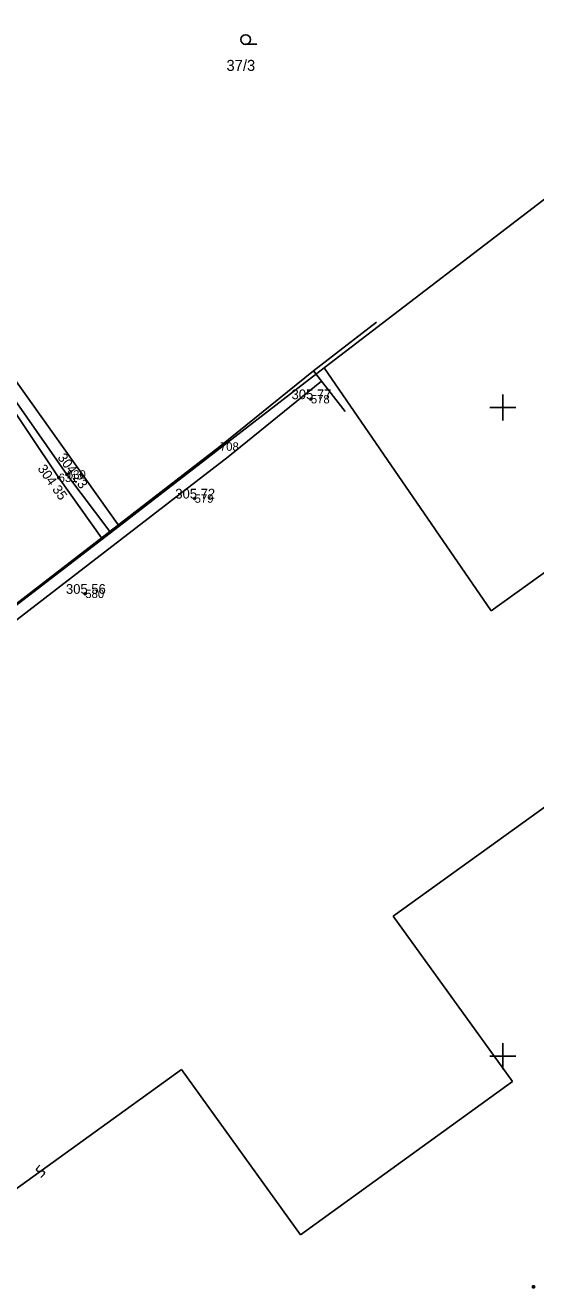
# Model space of a CAD drawing. Extents: x -492811 to -492366, y -1127107 to -1126748.
# Drawn here: x -492594.72 to -492578.99, y -1126927.14 to -1126888.22 of the extents above; entities that cross this region are included whole.
import ezdxf

# ---------------------------------------------------------------- set-up
doc = ezdxf.new("R2010")
doc.units = 0
for name, color, linetype in [('body', 7, 'Continuous'), ('katastrální mapa', 7, 'Continuous'), ('oplocení', 7, 'Continuous'), ('opěrná zeď', 7, 'Continuous'), ('podrobný výškový bod', 7, 'Continuous'), ('rozhraní ploch', 7, 'Continuous'), ('stavební objekt', 7, 'Continuous'), ('síť', 7, 'Continuous'), ('výšky', 7, 'Continuous'), ('čísla bodů', 7, 'Continuous')]:
    doc.layers.add(name, color=color, linetype=linetype)

msp = doc.modelspace()

# ---------------------------------------------------------------- linework, layer by layer
at = {"layer": 'body'}
for p, q in [((-492585.92, -1126899.748), (-492585.92, -1126899.748)), ((-492588.722, -1126901.209), (-492588.722, -1126901.209)), ((-492593.438, -1126902.068), (-492593.438, -1126902.068)), ((-492593.692, -1126902.171), (-492593.692, -1126902.171)), ((-492589.502, -1126902.811), (-492589.502, -1126902.811)), ((-492592.872, -1126905.748), (-492592.872, -1126905.748))]:
    msp.add_line(p, q, dxfattribs=at)
at = {"layer": 'katastrální mapa'}
for p, q in [((-492602.83, -1126888.22), (-492591.83, -1126903.66)), ((-492587.931, -1126888.807), (-492587.581, -1126888.807)), ((-492585.51, -1126898.78), (-492577.3, -1126892.49)), ((-492591.83, -1126903.66), (-492585.51, -1126898.78)), ((-492585.51, -1126898.78), (-492580.36, -1126906.27)), ((-492580.36, -1126906.27), (-492571.79, -1126900.09)), ((-492606.11, -1126914.64), (-492591.83, -1126903.66)), ((-492583.38, -1126915.69), (-492574.79, -1126909.49)), ((-492583.38, -1126915.69), (-492579.71, -1126920.78)), ((-492598.6, -1126926.69), (-492589.91, -1126920.41)), ((-492589.91, -1126920.41), (-492586.24, -1126925.51)), ((-492586.24, -1126925.51), (-492579.71, -1126920.78)), ((-492594.37, -1126923.46), (-492594.38, -1126923.52)), ((-492594.38, -1126923.52), (-492594.35, -1126923.55)), ((-492594.27, -1126923.36), (-492594.37, -1126923.46)), ((-492594.3, -1126923.56), (-492594.21, -1126923.54)), ((-492594.21, -1126923.54), (-492594.16, -1126923.55)), ((-492594.35, -1126923.55), (-492594.3, -1126923.56)), ((-492594.14, -1126923.64), (-492594.24, -1126923.74)), ((-492594.16, -1126923.55), (-492594.13, -1126923.58)), ((-492594.13, -1126923.58), (-492594.14, -1126923.64)), ((-492579.09, -1126927.08), (-492579.03, -1126927.08)), ((-492579.09, -1126927.14), (-492579.09, -1126927.08)), ((-492579.03, -1126927.14), (-492579.09, -1126927.14)), ((-492579.03, -1126927.08), (-492579.03, -1126927.14))]:
    msp.add_line(p, q, dxfattribs=at)
msp.add_circle((-492587.93, -1126888.661), 0.15, dxfattribs=at)
at = {"layer": 'oplocení'}
for p, q in [((-492593.438, -1126902.068), (-492595.736, -1126898.783)), ((-492592.115, -1126903.825), (-492593.438, -1126902.068))]:
    msp.add_line(p, q, dxfattribs=at)
at = {"layer": 'opěrná zeď'}
for p, q in [((-492585.835, -1126898.873), (-492588.722, -1126901.209)), ((-492585.59, -1126899.189), (-492588.474, -1126901.523)), ((-492588.722, -1126901.209), (-492601.107, -1126910.758)), ((-492588.474, -1126901.523), (-492600.863, -1126911.075))]:
    msp.add_line(p, q, dxfattribs=at)
at = {"layer": 'podrobný výškový bod'}
for centre in [(-492585.92, -1126899.748), (-492593.438, -1126902.068), (-492593.692, -1126902.171), (-492589.502, -1126902.811), (-492592.872, -1126905.748)]:
    msp.add_circle(centre, 0.03, dxfattribs=at)
at = {"layer": 'rozhraní ploch'}
for p, q in [((-492595.927, -1126898.827), (-492593.692, -1126902.171)), ((-492593.692, -1126902.171), (-492592.373, -1126904.024))]:
    msp.add_line(p, q, dxfattribs=at)
at = {"layer": 'stavební objekt'}
for p, q in [((-492585.835, -1126898.873), (-492583.894, -1126897.371)), ((-492584.865, -1126900.127), (-492585.835, -1126898.873))]:
    msp.add_line(p, q, dxfattribs=at)
at = {"layer": 'síť'}
for p, q in [((-492580, -1126899.6), (-492580, -1126900.4)), ((-492580.4, -1126900), (-492579.6, -1126900)), ((-492580, -1126919.6), (-492580, -1126920.4)), ((-492580.4, -1126920), (-492579.6, -1126920))]:
    msp.add_line(p, q, dxfattribs=at)

# ---------------------------------------------------------------- texts
at = {"layer": 'katastrální mapa'}
msp.add_text('37/3', height=0.34, dxfattribs=at).set_placement((-492588.521, -1126889.627))
at = {"layer": 'výšky'}
for s, p in [('305 77 ', (-492586.516, -1126899.748)), ('305 72 ', (-492590.098, -1126902.811)), ('305 56 ', (-492593.468, -1126905.748))]:
    msp.add_text(s, height=0.3, dxfattribs=at).set_placement(p)
for s, rotation, p in [('304 23 ', 306.3925, (-492593.742, -1126901.551)), ('304 35 ', 305.22, (-492594.356, -1126901.89))]:
    msp.add_text(s, height=0.3, rotation=rotation, dxfattribs=at).set_placement(p)
at = {"layer": 'čísla bodů'}
for s, p in [('578', (-492585.92, -1126899.878)), ('708', (-492588.722, -1126901.339)), ('631', (-492593.692, -1126902.301)), ('630', (-492593.438, -1126902.198)), ('579', (-492589.502, -1126902.941)), ('580', (-492592.872, -1126905.878))]:
    msp.add_text(s, height=0.26, dxfattribs=at).set_placement(p)

doc.saveas('drawing.dxf')
